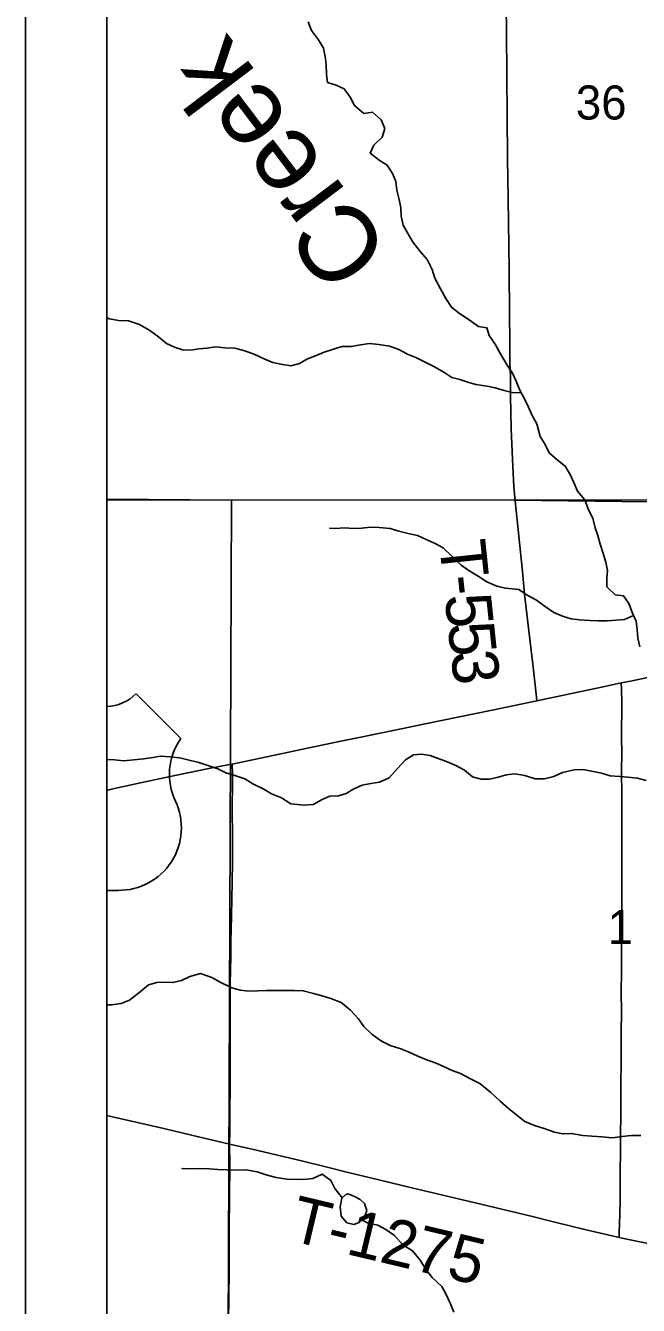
# Model space of a CAD drawing. Extents: x 0 to 34, y 0 to 22.
# Drawn here: x 2 to 2.753, y 15.888 to 17.462 of the extents above; entities that cross this region are included whole.
import ezdxf

# ---------------------------------------------------------------- set-up
doc = ezdxf.new("R2010")
doc.units = 0
for name, color, linetype in [('Default', 7, 'Continuous'), ('GM_X_Interstate_Route', 7, 'Continuous'), ('GM_X_Minor_Lake', 7, 'Continuous'), ('GM_X_Minor_River', 7, 'Continuous'), ('GM_X_Minor_River_Text', 7, 'Continuous'), ('GM_X_Section', 7, 'Continuous'), ('GM_X_Section_Text', 7, 'Continuous'), ('GM_X_Township_Road', 7, 'Continuous'), ('GM_X_Township_Road_Text', 7, 'Continuous'), ('GM_X_Unincorporated_Text', 7, 'Continuous'), ('GM_X_US_Route', 7, 'Continuous'), ('SH_Cut_Line', 7, 'Continuous'), ('SH_Data', 7, 'Continuous')]:
    doc.layers.add(name, color=color, linetype=linetype)

msp = doc.modelspace()

# ---------------------------------------------------------------- linework, layer by layer
at = {"layer": 'Default'}
for points in [[(2.1, 17.8727), (2.1, 16.8795), (2.253, 16.8782), (3.1023, 16.8785), (3.0924, 17.8824)], [(2.1, 16.8795), (2.1, 15.8527), (2.249, 15.8507), (2.253, 16.8782)]]:
    msp.add_lwpolyline(points, close=True, dxfattribs=at)
at = {"layer": 'GM_X_Interstate_Route'}
for points in [[(3.0331, 20.9), (2.1, 20.9), (2.1, 16.8784), (2.6014, 16.878), (3.0939, 16.8719), (3.0724, 18.2926), (3.0747, 18.8969), (3.067, 19.3838), (3.0588, 19.9042)], [(2.1, 16.8784), (2.1, 14.1), (3.2011, 14.1), (3.2037, 14.7782), (3.2041, 14.9016), (3.2042, 14.9221), (3.2098, 15.7617), (3.2111, 16.7578), (3.2115, 16.8719), (3.0939, 16.8719), (2.6014, 16.878)]]:
    msp.add_lwpolyline(points, close=True, dxfattribs=at)
at = {"layer": 'GM_X_Minor_Lake'}
for points in [[(2.4192, 16.0046), (2.4166, 16.013), (2.411, 16.018), (2.405, 16.0211), (2.4012, 16.023), (2.3963, 16.025), (2.3936, 16.0242), (2.3887, 16.0197), (2.3867, 16.0091), (2.3877, 15.9973), (2.3948, 15.9893), (2.4035, 15.9873), (2.41, 15.9895)], [(2.41, 15.9895), (2.4153, 15.9955), (2.4164, 15.9973), (2.4181, 16.0005), (2.4192, 16.0046)]]:
    msp.add_lwpolyline(points, dxfattribs=at)
at = {"layer": 'GM_X_Minor_River'}
for points in [[(2.3471, 17.4666), (2.3512, 17.4559), (2.3598, 17.4445), (2.3662, 17.4342), (2.368, 17.4239), (2.3694, 17.414), (2.3697, 17.4023), (2.3711, 17.392), (2.3817, 17.3885), (2.3915, 17.3842), (2.399, 17.3739), (2.4042, 17.3636), (2.4158, 17.3536), (2.4265, 17.3554), (2.437, 17.3462), (2.4414, 17.3355), (2.4383, 17.3246), (2.428, 17.3148), (2.4234, 17.305), (2.4347, 17.2965), (2.4445, 17.2903), (2.4508, 17.28), (2.4549, 17.2701), (2.4563, 17.2595), (2.4589, 17.2481), (2.4611, 17.2378), (2.4614, 17.2276), (2.4639, 17.2165), (2.4695, 17.207), (2.4762, 17.1952), (2.4852, 17.1837), (2.4935, 17.1741), (2.4998, 17.1619), (2.5031, 17.1513), (2.5098, 17.1383), (2.5165, 17.1261), (2.5233, 17.1154), (2.5334, 17.1077), (2.5451, 17.1), (2.5568, 17.0919), (2.567, 17.0903), (2.5699, 17.0808), (2.577, 17.0701), (2.5826, 17.0602), (2.592, 17.0442), (2.5983, 17.0342), (2.6028, 17.0247), (2.6072, 17.0144), (2.6136, 17.0022), (2.618, 16.9927), (2.6221, 16.9832), (2.6285, 16.9721), (2.6325, 16.9565), (2.6385, 16.9466), (2.6433, 16.9363), (2.6531, 16.9278), (2.6632, 16.9202), (2.6692, 16.9098), (2.6737, 16.8999), (2.6781, 16.8893), (2.6871, 16.8786), (2.6919, 16.8664), (2.6971, 16.8561), (2.7001, 16.8443), (2.7034, 16.8348), (2.7063, 16.8241), (2.71, 16.8127), (2.713, 16.802), (2.7152, 16.7918), (2.7143, 16.7823), (2.7142, 16.7717), (2.7247, 16.7617), (2.735, 16.7605), (2.7413, 16.7509), (2.7458, 16.7391), (2.7502, 16.7292), (2.7516, 16.7189), (2.7523, 16.7083), (2.7549, 16.6977)], [(2.6094, 17.0102), (2.5981, 17.0107), (2.5883, 17.0131), (2.577, 17.0162), (2.5671, 17.0182), (2.5535, 17.0206), (2.5437, 17.0234), (2.5335, 17.0265), (2.5237, 17.0289), (2.5139, 17.0358), (2.5018, 17.0424), (2.4901, 17.0482), (2.4796, 17.0536), (2.4694, 17.0579), (2.4585, 17.0637), (2.4471, 17.0676), (2.4343, 17.0696), (2.4225, 17.0709), (2.4115, 17.0691), (2.4002, 17.0673), (2.3888, 17.067), (2.377, 17.0637), (2.3668, 17.0604), (2.3561, 17.0556), (2.3463, 17.0519), (2.3368, 17.0463), (2.3261, 17.0433), (2.3159, 17.045), (2.3038, 17.0477), (2.294, 17.0516), (2.2816, 17.0574), (2.2695, 17.0617), (2.257, 17.0653), (2.2453, 17.0657), (2.2332, 17.0666), (2.2229, 17.0652), (2.2127, 17.0642), (2.2032, 17.0627), (2.193, 17.0632), (2.1828, 17.0664), (2.173, 17.071), (2.1632, 17.0791), (2.1527, 17.0868), (2.1399, 17.0941), (2.1263, 17.0988), (2.1142, 17.0993), (2.1032, 17.1013), (2.1, 17.1024)], [(2.7471, 16.7362), (2.7362, 16.7312), (2.726, 16.7306), (2.7146, 16.7299), (2.7036, 16.7297), (2.6934, 16.7301), (2.6809, 16.731), (2.6703, 16.7323), (2.6598, 16.7354), (2.6492, 16.74), (2.6375, 16.7481), (2.6278, 16.7551), (2.6164, 16.7612), (2.6063, 16.7682), (2.5896, 16.7698), (2.5791, 16.7722), (2.567, 16.7777), (2.5561, 16.7846), (2.5459, 16.7908), (2.5353, 16.7981), (2.5237, 16.8092), (2.5132, 16.8195), (2.5034, 16.8249), (2.4921, 16.8296), (2.4815, 16.8346), (2.4702, 16.837), (2.4588, 16.8402), (2.4479, 16.8433), (2.4346, 16.8446), (2.4237, 16.8451), (2.413, 16.8437), (2.4032, 16.8434), (2.3918, 16.8442), (2.3809, 16.8432), (2.3733, 16.8437)], [(2.7626, 16.5333), (2.752, 16.5364), (2.7403, 16.5373), (2.7304, 16.5381), (2.7183, 16.539), (2.7077, 16.5422), (2.6851, 16.5469), (2.6741, 16.5463), (2.6597, 16.543), (2.649, 16.5382), (2.6376, 16.5356), (2.6263, 16.5354), (2.6134, 16.5397), (2.6013, 16.5417), (2.5907, 16.5403), (2.5809, 16.5373), (2.5702, 16.5351), (2.56, 16.5352), (2.5491, 16.538), (2.5393, 16.5461), (2.5287, 16.5519), (2.5174, 16.5569), (2.5072, 16.5604), (2.4974, 16.5643), (2.4864, 16.5659), (2.4766, 16.5649), (2.4667, 16.5589), (2.4571, 16.548), (2.4468, 16.5367), (2.435, 16.5315), (2.4244, 16.5297), (2.4138, 16.5276), (2.4035, 16.5231), (2.394, 16.5175), (2.3845, 16.5146), (2.3739, 16.5139), (2.3644, 16.5098), (2.3534, 16.5039), (2.3424, 16.5032), (2.3261, 16.5045), (2.3144, 16.5122), (2.3024, 16.5169), (2.2926, 16.5227), (2.2794, 16.5292), (2.2696, 16.5354), (2.2571, 16.5397), (2.2462, 16.5429), (2.2364, 16.5479), (2.2239, 16.5518), (2.213, 16.5557), (2.2009, 16.5585), (2.1895, 16.5612), (2.1778, 16.5625), (2.1657, 16.5634), (2.1562, 16.5616), (2.1452, 16.5601), (2.1331, 16.5587), (2.1202, 16.5577), (2.1092, 16.5586), (2.1, 16.559)], [(2.7562, 16.0966), (2.7445, 16.0967), (2.7327, 16.0953), (2.7214, 16.0939), (2.7081, 16.0952), (2.696, 16.096), (2.685, 16.0969), (2.6711, 16.0993), (2.6597, 16.0987), (2.6499, 16.101), (2.6374, 16.1053), (2.6253, 16.1089), (2.6136, 16.1139), (2.6038, 16.1216), (2.5933, 16.13), (2.5832, 16.1389), (2.5719, 16.1496), (2.5584, 16.1607), (2.5459, 16.1669), (2.5346, 16.1731), (2.5244, 16.1766), (2.5146, 16.1813), (2.5044, 16.1856), (2.492, 16.1902), (2.4821, 16.1941), (2.4712, 16.1992), (2.461, 16.2034), (2.4482, 16.2073), (2.4372, 16.2128), (2.4256, 16.2212), (2.4158, 16.2308), (2.4087, 16.2407), (2.3993, 16.2507), (2.3877, 16.2603), (2.3752, 16.2654), (2.3646, 16.2685), (2.3537, 16.2713), (2.3412, 16.2748), (2.3302, 16.2749), (2.3181, 16.275), (2.2962, 16.2752), (2.2855, 16.2746), (2.2746, 16.2743), (2.2636, 16.2755), (2.2534, 16.2783), (2.2391, 16.2853), (2.2289, 16.2911), (2.2149, 16.2958), (2.202, 16.2921), (2.1914, 16.2873), (2.1811, 16.2847), (2.1713, 16.2852), (2.1614, 16.2849), (2.1512, 16.2819), (2.1386, 16.2718), (2.1276, 16.2632), (2.1173, 16.2591), (2.1059, 16.2573), (2.1, 16.2574)], [(2.3891, 16.0201), (2.3801, 16.0316), (2.3752, 16.0415), (2.3643, 16.0492), (2.3529, 16.044), (2.3419, 16.0426), (2.3211, 16.0428), (2.3078, 16.0452), (2.2969, 16.0479), (2.2844, 16.0522), (2.2712, 16.0546), (2.2595, 16.054), (2.2477, 16.0545), (2.2364, 16.055), (2.2258, 16.0558), (2.2133, 16.056), (2.203, 16.0557), (2.1924, 16.0562), (2.1928, 16.0558)], [(2.4117, 15.9946), (2.4117, 15.9947)], [(2.5264, 15.8795), (2.522, 15.8898), (2.5168, 15.9012), (2.5116, 15.9111), (2.4995, 15.9219), (2.4924, 15.9314), (2.4849, 15.9433), (2.4756, 15.9547), (2.4635, 15.9624), (2.4534, 15.9736), (2.4429, 15.9812), (2.4327, 15.9863), (2.421, 15.9887), (2.4129, 15.9928)]]:
    msp.add_lwpolyline(points, dxfattribs=at)
at = {"layer": 'GM_X_Section'}
msp.add_lwpolyline([(3.1023, 16.8785), (3.2153, 16.8759), (3.2082, 15.8593), (3.2075, 15.8525), (2.249, 15.8507), (2.253, 16.8782)], close=True, dxfattribs=at)
at = {"layer": 'GM_X_Township_Road'}
for points in [[(2.6016, 16.8774), (2.6001, 16.8945), (2.5993, 16.9114), (2.5985, 16.9287), (2.5968, 16.966), (2.596, 17.0064), (2.5958, 17.0313), (2.5952, 17.0468), (2.5953, 17.0748), (2.5948, 17.1059), (2.5944, 17.1618), (2.5932, 17.2489), (2.5924, 17.2986), (2.5918, 17.3514), (2.5916, 17.4012), (2.5909, 17.454), (2.5899, 17.5535)], [(2.6284, 16.6315), (2.6275, 16.6396), (2.6233, 16.6764), (2.6196, 16.7072), (2.6133, 16.7625), (2.6106, 16.7903), (2.6016, 16.8774)], [(2.7294, 15.9713), (2.7296, 15.9786), (2.7299, 15.9874), (2.7305, 16.0008), (2.7306, 16.0163), (2.7307, 16.0288), (2.7309, 16.0506), (2.7312, 16.0786), (2.7313, 16.0942), (2.7314, 16.1253), (2.7315, 16.1562), (2.7319, 16.1907), (2.7321, 16.2218), (2.7323, 16.2499), (2.7321, 16.2716), (2.7322, 16.2996), (2.7323, 16.3152), (2.7326, 16.3494), (2.7327, 16.3899), (2.7329, 16.4678), (2.7328, 16.4864), (2.7326, 16.5144), (2.7325, 16.5456), (2.7326, 16.5674), (2.7325, 16.5861), (2.7327, 16.6297), (2.7323, 16.6452), (2.732, 16.6533)], [(2.2507, 16.0862), (2.2508, 16.103), (2.2514, 16.1813), (2.2515, 16.2248), (2.2515, 16.2434), (2.2514, 16.2589), (2.2514, 16.2713), (2.2516, 16.2837), (2.2518, 16.2993), (2.2521, 16.3179), (2.2522, 16.3365), (2.2526, 16.3489), (2.2535, 16.3865), (2.2543, 16.4328), (2.2542, 16.4704), (2.2538, 16.4917), (2.2539, 16.501), (2.2542, 16.5289), (2.2542, 16.5413), (2.2538, 16.5536)], [(2.1, 16.1211), (2.1123, 16.1183), (2.1698, 16.1052), (2.2039, 16.0972), (2.2332, 16.0903), (2.2507, 16.0862)], [(2.2495, 15.8643), (2.2499, 15.9016), (2.2501, 15.9264), (2.2503, 15.9606), (2.2503, 15.9824), (2.2508, 16.0601), (2.2507, 16.0862)], [(2.2507, 16.0862), (2.2786, 16.0797), (2.339, 16.0654), (2.3722, 16.0575), (2.3933, 16.0521), (2.4356, 16.0418), (2.4748, 16.0322), (2.5594, 16.0121), (2.6229, 15.997), (2.644, 15.9917), (2.6772, 15.9834), (2.6923, 15.9798), (2.7104, 15.9756), (2.7294, 15.9713)], [(2.7294, 15.9713), (2.7313, 15.9707), (2.771, 15.9627), (2.7925, 15.9593), (2.814, 15.9558), (2.8201, 15.9546), (2.8261, 15.953), (2.832, 15.951), (2.8405, 15.9473), (2.8599, 15.9374), (2.8818, 15.9257), (2.9011, 15.9157), (2.9203, 15.9057), (2.9341, 15.8985), (2.945, 15.8926), (2.9751, 15.8764), (3.0045, 15.8611)]]:
    msp.add_lwpolyline(points, dxfattribs=at)
at = {"layer": 'GM_X_Unincorporated_Text'}
for p, q in [((2.1906, 16.5849), (2.1357, 16.6399)), ((2.1, 16.6242), (2.1, 16.3981)), ((2.1027, 16.3982), (2.1137, 16.3982))]:
    msp.add_line(p, q, dxfattribs=at)
for centre, radius, start, end in [((2.0972, 16.6791), 0.0549, 272.9037, 314.427), ((2.2536, 16.5408), 0.0769, 144.9991, 205.4529), ((2.1146, 16.4751), 0.0769, 269.3617, 25.1681), ((2.1027, 16.3432), 0.0549, 90, 92.8283)]:
    msp.add_arc(centre, radius, start, end, dxfattribs=at)
at = {"layer": 'GM_X_US_Route'}
msp.add_lwpolyline([(2.1, 16.5212), (2.1019, 16.5217), (2.1353, 16.5291), (2.1777, 16.5381), (2.2233, 16.5476), (2.2507, 16.5531), (2.2538, 16.5536), (2.275, 16.5581), (2.3024, 16.5639), (2.3328, 16.5701), (2.3541, 16.5747), (2.3875, 16.5816), (2.4119, 16.5865), (2.4636, 16.5973), (2.491, 16.603), (2.5732, 16.6199), (2.6284, 16.6315), (2.71, 16.6486), (2.732, 16.6533), (2.7435, 16.6557), (2.7861, 16.6645)], dxfattribs=at)
at = {"layer": 'SH_Cut_Line'}
msp.add_lwpolyline([(2.1, 20.9), (2.1, 14.1), (8.2568, 14.1)], dxfattribs=at)
at = {"layer": 'SH_Data'}
for p, q in [((2, 21), (2, 14)), ((2.1, 20.9), (2.1, 14.1))]:
    msp.add_line(p, q, dxfattribs=at)

# ---------------------------------------------------------------- texts
at = {"layer": 'GM_X_Minor_River_Text'}
msp.add_text('Creek', height=0.09473, rotation=127.1362, dxfattribs=at).set_placement((2.451, 17.1841))
at = {"layer": 'GM_X_Section_Text'}
for s, height, p in [('36', 0.04186, (2.6763, 17.3464)), ('1', 0.0419, (2.7154, 16.3322))]:
    msp.add_text(s, height=height, rotation=0, dxfattribs=at).set_placement(p)
at = {"layer": 'GM_X_Township_Road_Text'}
for s, height, rotation, p in [('T', 0.0568, 275.9852, (2.5081, 16.8264)), ('-', 0.0568, 275.9825, (2.5125, 16.7841)), ('5', 0.0568, 276.0177, (2.5149, 16.7609)), ('5', 0.0568, 276.0991, (2.5186, 16.726)), ('3', 0.0568, 276.48, (2.5224, 16.6908)), ('T-1275', 0.05682, 346.5861, (2.3224, 15.968))]:
    msp.add_text(s, height=height, rotation=rotation, dxfattribs=at).set_placement(p)

doc.saveas('drawing.dxf')
